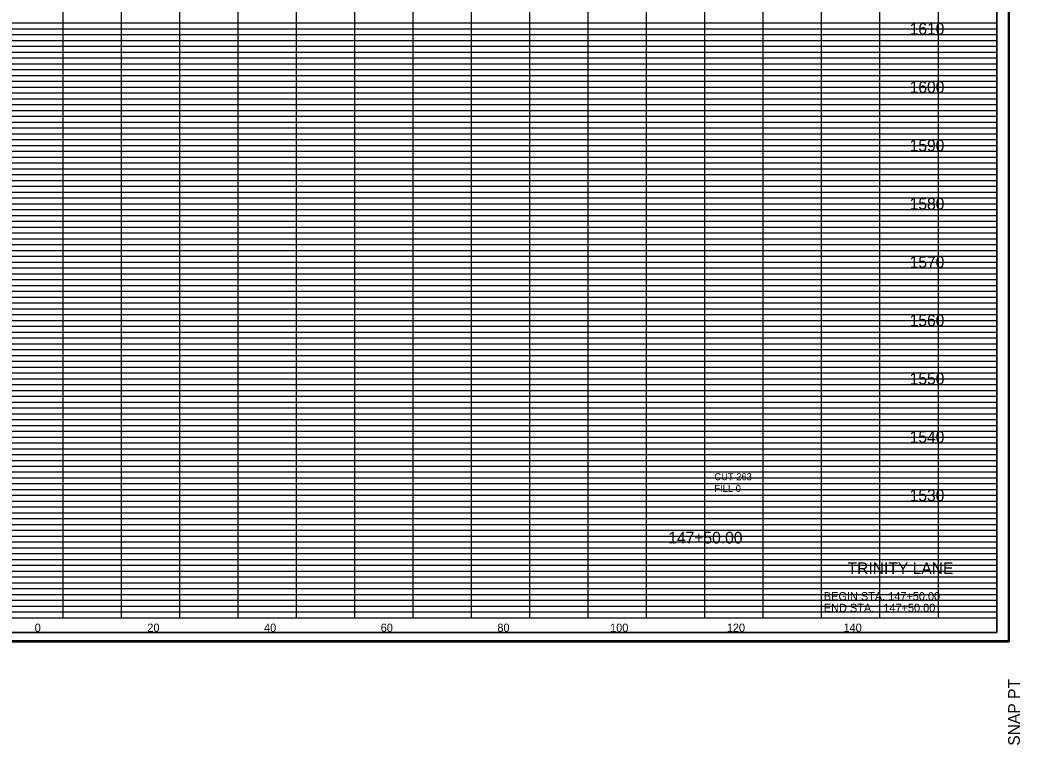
# Model space of a CAD drawing. Extents: x 980 to 1380, y 1248 to 3387.
# Drawn here: x 1152.6 to 1324, y 2058.2 to 2182.5 of the extents above; entities that cross this region are included whole.
import ezdxf

# ---------------------------------------------------------------- set-up
doc = ezdxf.new("R2010")
doc.units = 0
for name, color, linetype in [('DESIGN - SHEET - Corner Text', 7, 'Continuous'), ('DESIGN - SHEET - Light Grid', 7, 'Continuous'), ('DESIGN - SHEET - Linework', 7, 'Continuous'), ('DESIGN - SHEET - Plot Shape', 7, 'Continuous'), ('DESIGN - TYPICAL - Text', 7, 'Continuous')]:
    doc.layers.add(name, color=color, linetype=linetype)

# ---------------------------------------------------------------- blocks, each defined once
blk = doc.blocks.new('XSTSHT')
at = {"layer": 'DESIGN - SHEET - Light Grid'}
for p, q in [((8, 10.2), (16, 10.2)), ((16, 10.2), (24, 10.2)), ((24, 10.2), (32, 10.2)), ((8, 10.1), (16, 10.1)), ((16, 10.1), (24, 10.1)), ((24, 10.1), (32, 10.1)), ((8, 9.9), (16, 9.9)), ((8, 9.8), (16, 9.8)), ((16, 9.9), (24, 9.9)), ((16, 9.8), (24, 9.8)), ((24, 9.9), (32, 9.9)), ((24, 9.8), (32, 9.8)), ((8, 9.7), (16, 9.7)), ((8, 9.6), (16, 9.6)), ((16, 9.7), (24, 9.7)), ((16, 9.6), (24, 9.6)), ((24, 9.7), (32, 9.7)), ((24, 9.6), (32, 9.6)), ((8, 9.5), (16, 9.5)), ((16, 9.5), (24, 9.5)), ((24, 9.5), (32, 9.5)), ((8, 9.4), (16, 9.4)), ((8, 9.3), (16, 9.3)), ((16, 9.4), (24, 9.4)), ((16, 9.3), (24, 9.3)), ((24, 9.4), (32, 9.4)), ((24, 9.3), (32, 9.3)), ((8, 9.2), (16, 9.2)), ((8, 9.1), (16, 9.1)), ((16, 9.2), (24, 9.2)), ((16, 9.1), (24, 9.1)), ((24, 9.2), (32, 9.2)), ((24, 9.1), (32, 9.1)), ((8, 8.9), (16, 8.9)), ((8, 8.8), (16, 8.8)), ((16, 8.9), (24, 8.9)), ((16, 8.8), (24, 8.8)), ((24, 8.9), (32, 8.9)), ((24, 8.8), (32, 8.8)), ((8, 8.7), (16, 8.7)), ((8, 8.6), (16, 8.6)), ((16, 8.7), (24, 8.7)), ((16, 8.6), (24, 8.6)), ((24, 8.7), (32, 8.7)), ((24, 8.6), (32, 8.6)), ((8, 8.5), (16, 8.5)), ((8, 8.4), (16, 8.4)), ((16, 8.5), (24, 8.5)), ((16, 8.4), (24, 8.4)), ((24, 8.5), (32, 8.5)), ((24, 8.4), (32, 8.4)), ((8, 8.3), (16, 8.3)), ((16, 8.3), (24, 8.3)), ((24, 8.3), (32, 8.3)), ((8, 8.2), (16, 8.2)), ((8, 8.1), (16, 8.1)), ((16, 8.2), (24, 8.2)), ((16, 8.1), (24, 8.1)), ((24, 8.2), (32, 8.2)), ((24, 8.1), (32, 8.1)), ((8, 7.9), (16, 7.9)), ((16, 7.9), (24, 7.9)), ((24, 7.9), (32, 7.9)), ((8, 7.8), (16, 7.8)), ((16, 7.8), (24, 7.8)), ((24, 7.8), (32, 7.8)), ((8, 7.7), (16, 7.7)), ((8, 7.6), (16, 7.6)), ((16, 7.7), (24, 7.7)), ((16, 7.6), (24, 7.6)), ((24, 7.7), (32, 7.7)), ((24, 7.6), (32, 7.6)), ((8, 7.5), (16, 7.5)), ((8, 7.4), (16, 7.4)), ((16, 7.5), (24, 7.5)), ((16, 7.4), (24, 7.4)), ((24, 7.5), (32, 7.5)), ((24, 7.4), (32, 7.4)), ((8, 7.3), (16, 7.3)), ((8, 7.2), (16, 7.2)), ((16, 7.3), (24, 7.3)), ((16, 7.2), (24, 7.2)), ((24, 7.3), (32, 7.3)), ((24, 7.2), (32, 7.2)), ((8, 7.1), (16, 7.1)), ((16, 7.1), (24, 7.1)), ((24, 7.1), (32, 7.1)), ((8, 6.9), (16, 6.9)), ((16, 6.9), (24, 6.9)), ((24, 6.9), (32, 6.9)), ((8, 6.8), (16, 6.8)), ((8, 6.7), (16, 6.7)), ((16, 6.8), (24, 6.8)), ((16, 6.7), (24, 6.7)), ((24, 6.8), (32, 6.8)), ((24, 6.7), (32, 6.7)), ((8, 6.6), (16, 6.6)), ((16, 6.6), (24, 6.6)), ((24, 6.6), (32, 6.6)), ((8, 6.5), (16, 6.5)), ((8, 6.4), (16, 6.4)), ((16, 6.5), (24, 6.5)), ((16, 6.4), (24, 6.4)), ((24, 6.5), (32, 6.5)), ((24, 6.4), (32, 6.4)), ((8, 6.3), (16, 6.3)), ((8, 6.2), (16, 6.2)), ((16, 6.3), (24, 6.3)), ((16, 6.2), (24, 6.2)), ((24, 6.3), (32, 6.3)), ((24, 6.2), (32, 6.2)), ((8, 6.1), (16, 6.1)), ((16, 6.1), (24, 6.1)), ((24, 6.1), (32, 6.1)), ((8, 5.9), (16, 5.9)), ((16, 5.9), (24, 5.9)), ((24, 5.9), (32, 5.9)), ((8, 5.8), (16, 5.8)), ((8, 5.7), (16, 5.7)), ((16, 5.8), (24, 5.8)), ((16, 5.7), (24, 5.7)), ((24, 5.8), (32, 5.8)), ((24, 5.7), (32, 5.7)), ((8, 5.6), (16, 5.6)), ((8, 5.5), (16, 5.5)), ((16, 5.6), (24, 5.6)), ((16, 5.5), (24, 5.5)), ((24, 5.6), (32, 5.6)), ((24, 5.5), (32, 5.5)), ((8, 5.4), (16, 5.4)), ((16, 5.4), (24, 5.4)), ((24, 5.4), (32, 5.4)), ((8, 5.3), (16, 5.3)), ((8, 5.2), (16, 5.2)), ((16, 5.3), (24, 5.3)), ((16, 5.2), (24, 5.2)), ((24, 5.3), (32, 5.3)), ((24, 5.2), (32, 5.2)), ((8, 5.1), (16, 5.1)), ((16, 5.1), (24, 5.1)), ((24, 5.1), (32, 5.1)), ((8, 4.9), (16, 4.9)), ((8, 4.8), (16, 4.8)), ((16, 4.9), (24, 4.9)), ((16, 4.8), (24, 4.8)), ((24, 4.9), (32, 4.9)), ((24, 4.8), (32, 4.8)), ((8, 4.7), (16, 4.7)), ((16, 4.7), (24, 4.7)), ((24, 4.7), (32, 4.7)), ((8, 4.6), (16, 4.6)), ((8, 4.5), (16, 4.5)), ((16, 4.6), (24, 4.6)), ((16, 4.5), (24, 4.5)), ((24, 4.6), (32, 4.6)), ((24, 4.5), (32, 4.5)), ((8, 4.4), (16, 4.4)), ((8, 4.3), (16, 4.3)), ((16, 4.4), (24, 4.4)), ((16, 4.3), (24, 4.3)), ((24, 4.4), (32, 4.4)), ((24, 4.3), (32, 4.3)), ((8, 4.2), (16, 4.2)), ((16, 4.2), (24, 4.2)), ((24, 4.2), (32, 4.2)), ((8, 4.1), (16, 4.1)), ((16, 4.1), (24, 4.1)), ((24, 4.1), (32, 4.1)), ((8, 3.9), (16, 3.9)), ((8, 3.8), (16, 3.8)), ((16, 3.9), (24, 3.9)), ((16, 3.8), (24, 3.8)), ((24, 3.9), (32, 3.9)), ((24, 3.8), (32, 3.8)), ((8, 3.7), (16, 3.7)), ((8, 3.6), (16, 3.6)), ((16, 3.7), (24, 3.7)), ((16, 3.6), (24, 3.6)), ((24, 3.7), (32, 3.7)), ((24, 3.6), (32, 3.6)), ((8, 3.5), (16, 3.5)), ((16, 3.5), (24, 3.5)), ((24, 3.5), (32, 3.5)), ((8, 3.4), (16, 3.4)), ((8, 3.3), (16, 3.3)), ((16, 3.4), (24, 3.4)), ((16, 3.3), (24, 3.3)), ((24, 3.4), (32, 3.4)), ((24, 3.3), (32, 3.3)), ((8, 3.2), (16, 3.2)), ((8, 3.1), (16, 3.1)), ((16, 3.2), (24, 3.2)), ((16, 3.1), (24, 3.1)), ((24, 3.2), (32, 3.2)), ((24, 3.1), (32, 3.1)), ((8, 2.9), (16, 2.9)), ((8, 2.8), (16, 2.8)), ((16, 2.9), (24, 2.9)), ((16, 2.8), (24, 2.8)), ((24, 2.9), (32, 2.9)), ((24, 2.8), (32, 2.8)), ((8, 2.7), (16, 2.7)), ((8, 2.6), (16, 2.6)), ((16, 2.7), (24, 2.7)), ((16, 2.6), (24, 2.6)), ((24, 2.7), (32, 2.7)), ((24, 2.6), (32, 2.6)), ((8, 2.5), (16, 2.5)), ((8, 2.4), (16, 2.4)), ((16, 2.5), (24, 2.5)), ((16, 2.4), (24, 2.4)), ((24, 2.5), (32, 2.5)), ((24, 2.4), (32, 2.4)), ((8, 2.3), (16, 2.3)), ((16, 2.3), (24, 2.3)), ((24, 2.3), (32, 2.3)), ((8, 2.2), (16, 2.2)), ((8, 2.1), (16, 2.1)), ((16, 2.2), (24, 2.2)), ((16, 2.1), (24, 2.1)), ((24, 2.2), (32, 2.2)), ((24, 2.1), (32, 2.1)), ((8, 1.9), (16, 1.9)), ((16, 1.9), (24, 1.9)), ((24, 1.9), (32, 1.9)), ((8, 1.8), (16, 1.8)), ((16, 1.8), (24, 1.8)), ((24, 1.8), (32, 1.8)), ((8, 1.7), (16, 1.7)), ((8, 1.6), (16, 1.6)), ((16, 1.7), (24, 1.7)), ((16, 1.6), (24, 1.6)), ((24, 1.7), (32, 1.7)), ((24, 1.6), (32, 1.6)), ((8, 1.5), (16, 1.5)), ((8, 1.4), (16, 1.4)), ((16, 1.5), (24, 1.5)), ((16, 1.4), (24, 1.4)), ((24, 1.5), (32, 1.5)), ((24, 1.4), (32, 1.4)), ((8, 1.3), (16, 1.3)), ((8, 1.2), (16, 1.2)), ((16, 1.3), (24, 1.3)), ((16, 1.2), (24, 1.2)), ((24, 1.3), (32, 1.3)), ((24, 1.2), (32, 1.2)), ((8, 1.1), (16, 1.1)), ((16, 1.1), (24, 1.1)), ((24, 1.1), (32, 1.1)), ((8, 0.9), (16, 0.9)), ((16, 0.9), (24, 0.9)), ((24, 0.9), (32, 0.9)), ((8, 0.8), (16, 0.8)), ((8, 0.7), (16, 0.7)), ((16, 0.8), (24, 0.8)), ((16, 0.7), (24, 0.7)), ((24, 0.8), (32, 0.8)), ((24, 0.7), (32, 0.7)), ((8, 0.6), (16, 0.6)), ((16, 0.6), (24, 0.6)), ((24, 0.6), (32, 0.6)), ((8, 0.5), (16, 0.5)), ((8, 0.4), (16, 0.4)), ((16, 0.5), (24, 0.5)), ((16, 0.4), (24, 0.4)), ((24, 0.5), (32, 0.5)), ((24, 0.4), (32, 0.4)), ((8, 0.3), (16, 0.3)), ((8, 0.2), (16, 0.2)), ((16, 0.3), (24, 0.3)), ((16, 0.2), (24, 0.2)), ((24, 0.3), (32, 0.3)), ((24, 0.2), (32, 0.2)), ((8, 0.1), (16, 0.1)), ((16, 0.1), (24, 0.1)), ((24, 0.1), (32, 0.1))]:
    blk.add_line(p, q, dxfattribs=at)
at = {"layer": 'DESIGN - SHEET - Linework'}
for p, q in [((32.217, 21.414), (32.217, -0.414)), ((16, 0), (16, 21)), ((17, 0), (17, 21)), ((18, 0), (18, 21)), ((19, 0), (19, 21)), ((20, 0), (20, 21)), ((21, 0), (21, 21)), ((22, 0), (22, 21)), ((23, 0), (23, 21)), ((24, 0), (24, 21)), ((25, 0), (25, 21)), ((26, 0), (26, 21)), ((27, 0), (27, 21)), ((28, 0), (28, 20)), ((29, 0), (29, 20)), ((30, 0), (30, 20)), ((31, 0), (31, 20)), ((0, 10), (32, 10)), ((0, 9), (32, 9)), ((0, 8), (32, 8)), ((0, 7), (32, 7)), ((0, 6), (32, 6)), ((0, 5), (32, 5)), ((0, 4), (32, 4)), ((0, 3), (32, 3)), ((0, 2), (32, 2)), ((0, 1), (32, 1)), ((-1.823, -0.414), (32.217, -0.414))]:
    blk.add_line(p, q, dxfattribs=at)
blk.add_lwpolyline([(0, 21), (0, 0), (32, 0), (32, 21), (0, 21)], dxfattribs=at)
at = {"layer": 'DESIGN - SHEET - Plot Shape'}
for points in [[(-1.803, 21.394), (32.197, 21.394), (32.197, -0.394), (-1.803, -0.394)], [(-0.85, 21), (32, 21), (32, -0.25), (-0.85, -0.25)]]:
    blk.add_lwpolyline(points, close=True, dxfattribs=at)
at = {"layer": 'DESIGN - SHEET - Corner Text'}
blk.add_text('SNAP PT  ', height=0.2, rotation=90, dxfattribs=at).set_placement((32.397, -2.194))

msp = doc.modelspace()

# ---------------------------------------------------------------- linework, layer by layer
at = {"layer": 'DESIGN - SHEET - Plot Shape'}
msp.add_lwpolyline([(991.5, 2077.5), (1320, 2077.5), (1320, 2290), (991.5, 2290)], close=True, dxfattribs=at)

# ---------------------------------------------------------------- block references
at = {"layer": 'DESIGN - TYPICAL - Text', "xscale": 10, "yscale": 10}
msp.add_blockref('XSTSHT', (1000, 2080), dxfattribs=at)

# ---------------------------------------------------------------- texts
at = {"layer": 'DESIGN - SHEET - Corner Text'}
for s, height, p in [('TRINITY LANE', 2, (1294.45, 2087.5)), ('BEGIN STA. 147+50.00', 1.4, (1290.38, 2083)), ('END STA.   147+50.00', 1.4, (1290.38, 2081))]:
    msp.add_text(s, height=height, dxfattribs=at).set_placement(p)
at = {"layer": 'DESIGN - TYPICAL - Text'}
for s, height, p in [('     1610     ', 2, (1301.37, 2180)), ('     1600     ', 2, (1301.37, 2170)), ('     1590     ', 2, (1301.37, 2160)), ('     1580     ', 2, (1301.37, 2150)), ('     1570     ', 2, (1301.37, 2140)), ('     1560     ', 2, (1301.37, 2130)), ('     1550     ', 2, (1301.37, 2120)), ('     1540     ', 2, (1301.37, 2110)), ('CUT 263', 1.2, (1271.61, 2103.59)), ('FILL 0', 1.2, (1271.61, 2101.59)), ('     1530     ', 2, (1301.37, 2100)), ('     147+50.00     ', 2, (1260, 2092.74)), ('     0     ', 1.4, (1152.51, 2077.6)), ('     0     ', 1.4, (1152.51, 2077.6)), ('     20     ', 1.4, (1171.82, 2077.6)), ('     40     ', 1.4, (1191.82, 2077.6)), ('     60     ', 1.4, (1211.82, 2077.6)), ('     80     ', 1.4, (1231.82, 2077.6)), ('     100     ', 1.4, (1251.14, 2077.6)), ('     120     ', 1.4, (1271.14, 2077.6)), ('     140     ', 1.4, (1291.14, 2077.6))]:
    msp.add_text(s, height=height, dxfattribs=at).set_placement(p)

doc.saveas('drawing.dxf')
